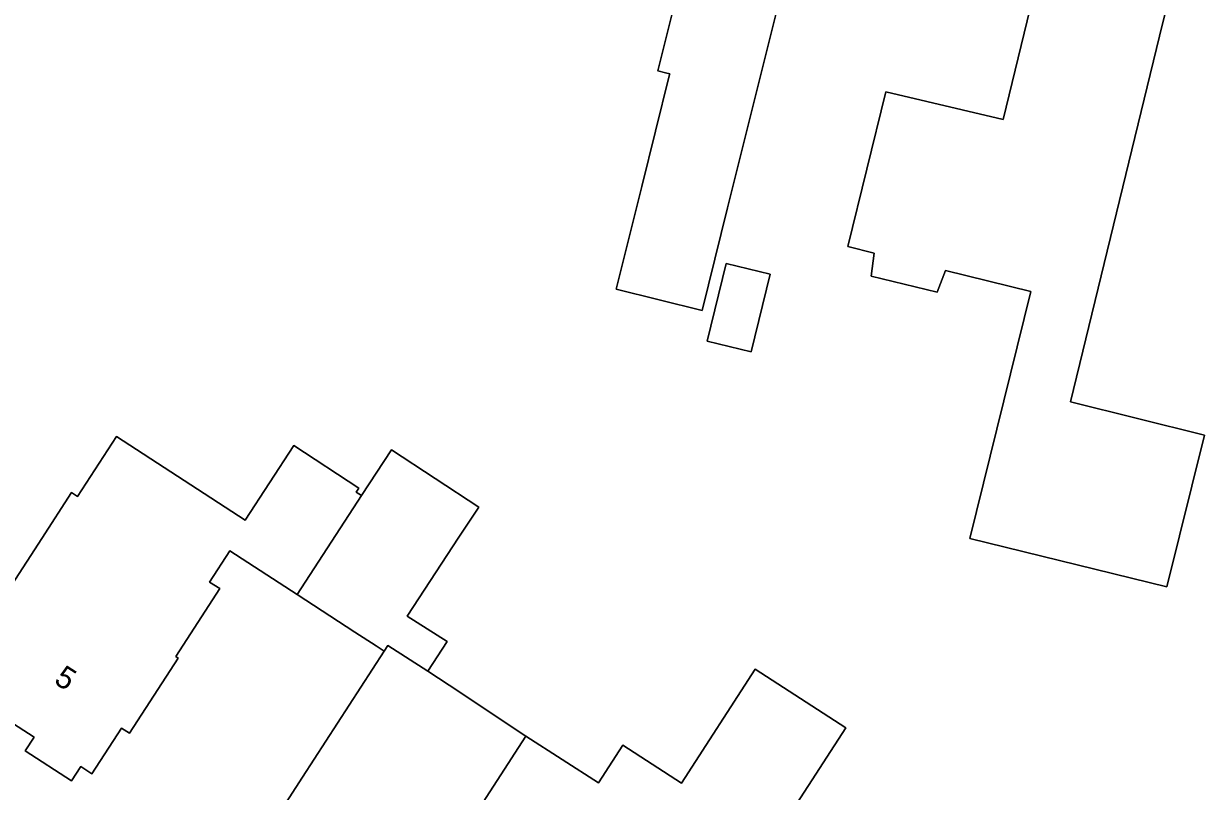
# Model space of a CAD drawing. Extents: x 161139 to 161601, y 381708 to 382245.
# Drawn here: x 161422.2 to 161475.6, y 382109.7 to 382144.4 of the extents above; entities that cross this region are included whole.
import ezdxf

# ---------------------------------------------------------------- set-up
doc = ezdxf.new("R2010")
doc.units = 0
for name, color, linetype in [('IMGEO_Erf', 7, 'Continuous'), ('IMGEO_Pand', 7, 'Continuous'), ('IMGEO_Pand_nummerreeks', 7, 'Continuous')]:
    doc.layers.add(name, color=color, linetype=linetype)

msp = doc.modelspace()

# ---------------------------------------------------------------- linework, layer by layer
at = {"layer": 'IMGEO_Erf'}
for points in [[(161454.038, 382136.105), (161452.882, 382131.461), (161449.001, 382132.427), (161450.157, 382137.072), (161451.402, 382142.074), (161451.423, 382142.158), (161451.237, 382142.204), (161450.889, 382142.291), (161451.929, 382146.469), (161451.502, 382146.575), (161446.44, 382147.835), (161447.045, 382150.266), (161440.526, 382151.889), (161442.225, 382158.711), (161443.433, 382163.562), (161455.013, 382160.679), (161453.805, 382155.828), (161452.051, 382148.781), (161456.893, 382147.575)], [(161455.111, 382129.583), (161453.11, 382130.071), (161453.969, 382133.591), (161455.97, 382133.103)]]:
    msp.add_lwpolyline(points, close=True, dxfattribs=at)
for points in [[(161474.406, 382147.295), (161473.571, 382143.873), (161469.54, 382127.323), (161475.595, 382125.827), (161473.898, 382118.954), (161464.986, 382121.154), (161467.743, 382132.322), (161463.889, 382133.273), (161463.511, 382132.295), (161460.537, 382133.016), (161460.658, 382134.056), (161459.473, 382134.346), (161461.186, 382141.344), (161466.492, 382140.097), (161468.93, 382150.099)], [(161420.311, 382116.952), (161423.028, 382121.15), (161424.369, 382123.223), (161424.649, 382123.042), (161426.411, 382125.757), (161432.231, 382121.978), (161434.42, 382125.349), (161437.371, 382123.43), (161437.252, 382123.247), (161437.484, 382123.096), (161438.836, 382125.164), (161442.785, 382122.568), (161441.891, 382121.207), (161439.546, 382117.641), (161441.356, 382116.489), (161440.486, 382115.143), (161441.455, 382114.516), (161444.922, 382112.208), (161448.197, 382110.09), (161449.302, 382111.799), (161451.951, 382110.085), (161455.281, 382115.234), (161459.379, 382112.577), (161453.77, 382103.907)], [(161432.104, 382106.149), (161434.82, 382110.347), (161438.514, 382116.055), (161438.153, 382116.29), (161437.189, 382116.917), (161434.584, 382118.612), (161431.54, 382120.593), (161430.619, 382119.179), (161431.074, 382118.885), (161429.086, 382115.814), (161429.204, 382115.738), (161427.002, 382112.335), (161426.632, 382112.574), (161425.295, 382110.508), (161424.796, 382110.831), (161424.378, 382110.185), (161422.284, 382111.54), (161422.684, 382112.158), (161419.524, 382114.203)]]:
    msp.add_lwpolyline(points, dxfattribs=at)
at = {"layer": 'IMGEO_Pand'}
for points in [[(161453.805, 382155.828), (161455.013, 382160.679), (161443.433, 382163.562), (161442.225, 382158.711), (161440.526, 382151.889), (161447.045, 382150.266), (161446.44, 382147.835), (161451.502, 382146.575), (161451.929, 382146.469), (161450.889, 382142.291), (161451.237, 382142.204), (161451.423, 382142.158), (161451.402, 382142.074), (161450.157, 382137.072), (161449.001, 382132.427), (161452.882, 382131.461), (161454.038, 382136.105), (161456.893, 382147.575), (161452.051, 382148.781)], [(161453.11, 382130.071), (161455.111, 382129.583), (161455.97, 382133.103), (161453.969, 382133.591)], [(161441.891, 382121.207), (161442.785, 382122.568), (161438.836, 382125.164), (161437.484, 382123.096), (161434.584, 382118.612), (161437.189, 382116.917), (161438.153, 382116.29), (161438.514, 382116.055), (161438.679, 382116.311), (161440.486, 382115.143), (161441.356, 382116.489), (161439.546, 382117.641)], [(161444.922, 382112.208), (161441.455, 382114.516), (161440.486, 382115.143), (161438.679, 382116.311), (161438.514, 382116.055), (161434.82, 382110.347), (161432.104, 382106.149), (161435.385, 382104.027), (161434.978, 382103.397), (161437.966, 382101.463)], [(161450.002, 382106.345), (161453.77, 382103.907), (161459.379, 382112.577), (161455.281, 382115.234), (161451.951, 382110.085), (161449.302, 382111.799), (161448.197, 382110.09), (161444.922, 382112.208), (161437.966, 382101.463), (161440.952, 382099.531), (161441.366, 382100.171), (161444.638, 382098.054), (161447.354, 382102.252)]]:
    msp.add_lwpolyline(points, close=True, dxfattribs=at)
for points in [[(161468.93, 382150.099), (161466.492, 382140.097), (161461.186, 382141.344), (161459.473, 382134.346), (161460.658, 382134.056), (161460.537, 382133.016), (161463.511, 382132.295), (161463.889, 382133.273), (161467.743, 382132.322), (161464.986, 382121.154), (161473.898, 382118.954), (161475.595, 382125.827), (161469.54, 382127.323), (161473.571, 382143.873), (161474.406, 382147.295)], [(161419.524, 382114.203), (161422.684, 382112.158), (161422.284, 382111.54), (161424.378, 382110.185), (161424.796, 382110.831), (161425.295, 382110.508), (161426.632, 382112.574), (161427.002, 382112.335), (161429.204, 382115.738), (161429.086, 382115.814), (161431.074, 382118.885), (161430.619, 382119.179), (161431.54, 382120.593), (161434.584, 382118.612), (161437.484, 382123.096), (161437.252, 382123.247), (161437.371, 382123.43), (161434.42, 382125.349), (161432.231, 382121.978), (161426.411, 382125.757), (161424.649, 382123.042), (161424.369, 382123.223), (161423.028, 382121.15), (161420.311, 382116.952)]]:
    msp.add_lwpolyline(points, dxfattribs=at)

# ---------------------------------------------------------------- texts
at = {"layer": 'IMGEO_Pand_nummerreeks'}
msp.add_text('5', height=1, rotation=327.3698, dxfattribs=at).set_placement((161423.536, 382114.626))

doc.saveas('drawing.dxf')
